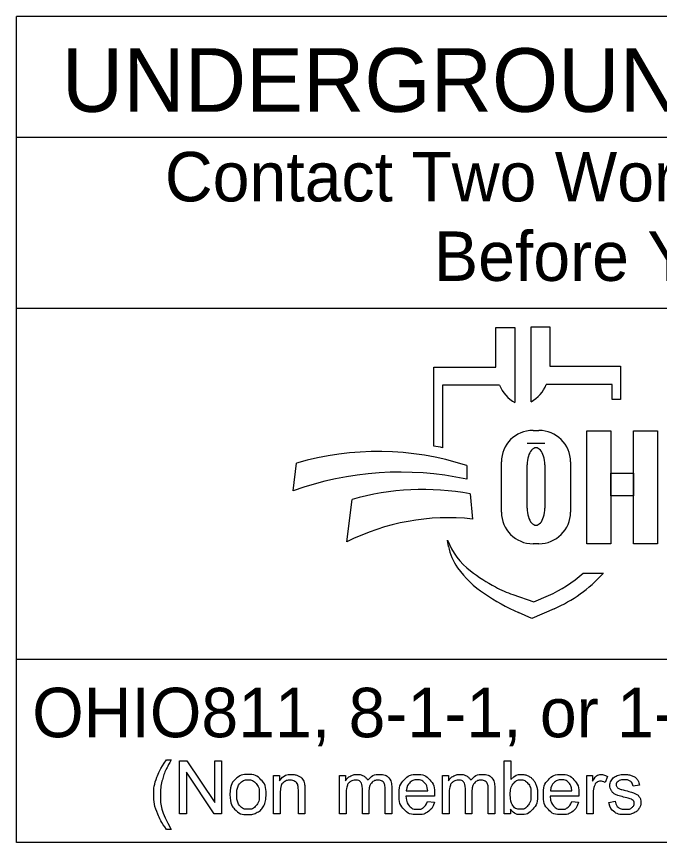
# Model space of a CAD drawing. Extents: x 0 to 34, y 0 to 22.
# Drawn here: x 14.755 to 16.574, y 1.201 to 3.539 of the extents above; entities that cross this region are included whole.
import ezdxf

# ---------------------------------------------------------------- set-up
doc = ezdxf.new("R2010")
doc.units = 0
doc.layers.add('SH_Data', color=7, linetype='Continuous')
doc.layers.add('SH_Text', color=7, linetype='Continuous')

msp = doc.modelspace()

# ---------------------------------------------------------------- linework, layer by layer
at = {"layer": 'SH_Data'}
for p, q in [((14.7549, 1.2013), (14.7549, 3.5388)), ((19.0049, 3.5388), (14.7549, 3.5388)), ((14.7549, 3.1972), (19.0049, 3.1972)), ((14.7549, 2.7138), (19.0049, 2.7138)), ((19.0049, 1.7191), (14.7549, 1.7191)), ((19.0049, 1.2013), (14.7549, 1.2013))]:
    msp.add_line(p, q, dxfattribs=at)
at = {"layer": 'SH_Text'}
for p, q in [((16.1109, 2.5468), (16.1109, 2.6583)), ((16.1109, 2.6583), (16.1645, 2.6583)), ((16.1645, 2.6583), (16.1645, 2.4462)), ((16.2102, 2.4485), (16.2102, 2.6606)), ((16.2102, 2.6606), (16.2638, 2.6606)), ((16.2638, 2.6606), (16.2638, 2.5491)), ((16.2638, 2.5491), (16.4631, 2.5491)), ((16.4631, 2.5491), (16.4631, 2.4553)), ((15.9349, 2.3229), (15.9349, 2.5468)), ((15.9349, 2.5468), (16.1109, 2.5468)), ((15.9602, 2.4953), (15.9602, 2.3185)), ((16.1213, 2.4953), (15.9602, 2.4953)), ((16.4398, 2.4977), (16.2534, 2.4977)), ((16.4398, 2.4553), (16.4398, 2.4977)), ((16.4631, 2.4553), (16.4398, 2.4553)), ((16.2159, 2.3676), (16.2324, 2.3676)), ((16.2492, 2.3306), (16.1994, 2.3306)), ((15.5376, 2.1966), (15.547, 2.2747)), ((16.0282, 2.2682), (16.0282, 2.2294)), ((16.1264, 2.1361), (16.1264, 2.2781)), ((16.1993, 2.1475), (16.1993, 2.2699)), ((16.2491, 2.2699), (16.2491, 2.1475)), ((16.3219, 2.2781), (16.3219, 2.1361)), ((16.0382, 2.1876), (16.0444, 2.1167)), ((15.6894, 2.0521), (15.7041, 2.1722)), ((15.9771, 2.0392), (15.974, 2.0571)), ((16.2324, 2.0467), (16.2159, 2.0467)), ((16.3574, 1.9633), (16.4148, 1.9633)), ((16.159, 1.9029), (16.2184, 1.8824)), ((16.2184, 1.8824), (16.2594, 1.9002)), ((16.2124, 1.8354), (16.175, 1.8519)), ((16.2756, 1.8629), (16.2124, 1.8354))]:
    msp.add_line(p, q, dxfattribs=at)
for points in [[(16.3683, 2.3666), (16.4363, 2.3666), (16.4363, 2.0466), (16.3683, 2.0466)], [(16.5005, 2.3666), (16.5684, 2.3666), (16.5684, 2.0466), (16.5005, 2.0466)], [(16.4363, 2.2467), (16.5005, 2.2467), (16.5005, 2.1827), (16.4363, 2.1827)]]:
    msp.add_lwpolyline(points, close=True, dxfattribs=at)
for points in [[(15.1795, 1.4351), (15.1927, 1.4351)], [(15.2162, 1.2824), (15.2162, 1.4326), (15.2366, 1.4326), (15.3156, 1.3146), (15.3156, 1.4326), (15.3346, 1.4326), (15.3346, 1.2824), (15.3142, 1.2824), (15.2352, 1.4003), (15.2352, 1.2824), (15.2162, 1.2824)], [(16.1517, 1.2824), (16.1346, 1.2824), (16.1346, 1.4326), (16.1531, 1.4326), (16.1531, 1.3791)], [(15.4822, 1.2824), (15.4822, 1.3913), (15.4988, 1.3913), (15.4988, 1.3758)], [(15.6686, 1.2824), (15.6686, 1.3913), (15.6851, 1.3913), (15.6851, 1.3759)], [(15.96, 1.2824), (15.96, 1.3913), (15.9765, 1.3913), (15.9765, 1.3759)], [(16.3678, 1.2824), (16.3678, 1.3913), (16.3844, 1.3913), (16.3844, 1.3748)], [(16.4268, 1.3878), (16.4204, 1.3707)], [(15.8161, 1.3571), (15.8161, 1.2824), (15.7977, 1.2824), (15.7977, 1.3509)], [(16.1075, 1.3571), (16.1075, 1.2824), (16.0891, 1.2824), (16.0891, 1.3509)], [(16.5168, 1.3631), (16.4987, 1.3607)], [(15.5006, 1.3418), (15.5006, 1.2824), (15.4822, 1.2824)], [(15.5705, 1.3493), (15.5705, 1.2824), (15.5521, 1.2824), (15.5521, 1.3486)], [(15.687, 1.3388), (15.687, 1.2824), (15.6686, 1.2824)], [(15.7517, 1.3456), (15.7517, 1.2824), (15.7333, 1.2824), (15.7333, 1.3531)], [(15.8572, 1.3472), (15.918, 1.3472)], [(15.9784, 1.3388), (15.9784, 1.2824), (15.96, 1.2824)], [(16.0431, 1.3456), (16.0431, 1.2824), (16.0246, 1.2824), (16.0246, 1.3531)], [(16.2652, 1.3472), (16.326, 1.3472)], [(16.3862, 1.3394), (16.3862, 1.2824), (16.3678, 1.2824)], [(15.9374, 1.3321), (15.8562, 1.3321)], [(15.9178, 1.3176), (15.9368, 1.3151)], [(16.3453, 1.3321), (16.2642, 1.3321)], [(16.3258, 1.3176), (16.3448, 1.3151)], [(16.4304, 1.3149), (16.4486, 1.3178)], [(16.1517, 1.296), (16.1517, 1.2824)], [(15.1927, 1.2382), (15.1795, 1.2382)]]:
    msp.add_lwpolyline(points, dxfattribs=at)
for centre, radius, start, end in [((16.2127, 2.5321), 0.0985, 201.9296, 240.7469), ((16.1621, 2.5344), 0.0985, 299.2531, 338.0704), ((16.2159, 2.2781), 0.0895, 90, 180), ((16.2324, 2.2781), 0.0895, 0, 90), ((15.8068, 1.5139), 0.8191, 79.2074, 81.0007), ((15.777, 1.4886), 0.8191, 72.1402, 106.3144), ((15.8401, 1.3575), 0.8919, 77.8238, 109.8274), ((15.904, 1.4679), 0.7322, 79.44, 105.8467), ((16.2159, 2.1361), 0.0895, 180, 270), ((16.2324, 2.1361), 0.0895, 270, 0), ((15.9761, 1.4847), 0.6357, 83.8248, 116.8021), ((16.1614, 2.1292), 0.2008, 201.0457, 232.5314), ((16.1184, 2.0633), 0.1433, 189.6817, 216.0884), ((16.2521, 2.1607), 0.3088, 216.0884, 235.7167), ((16.354, 2.3804), 0.5173, 232.5314, 241.794), ((16.116, 2.2307), 0.3602, 293.4582, 312.0712), ((16.116, 2.2307), 0.401, 293.4582, 317.8286), ((16.2688, 2.2216), 0.3371, 241.794, 250.9821), ((16.4186, 2.405), 0.6044, 235.7167, 246.2325)]:
    msp.add_arc(centre, radius, start, end, dxfattribs=at)
for centre, start_param, end_param in [((16.2242, 2.2699), 4.712389, 7.853982), ((16.2242, 2.1475), 1.570796, 4.712389)]:
    msp.add_ellipse(centre, major_axis=(0, 0.0484), ratio=0.514403, start_param=start_param, end_param=end_param, dxfattribs=at)
for points in [[(15.1795, 1.2382), (15.1642, 1.2575), (15.1537, 1.2833), (15.1431, 1.3091), (15.1431, 1.3368), (15.1431, 1.3611), (15.151, 1.3835), (15.1602, 1.4094), (15.1795, 1.4351)], [(15.1927, 1.4351), (15.1803, 1.4138), (15.1763, 1.4047), (15.1701, 1.3905), (15.1665, 1.3752), (15.1621, 1.356), (15.1621, 1.3367), (15.1621, 1.2874), (15.1927, 1.2382)], [(15.3587, 1.3368), (15.3587, 1.367), (15.3755, 1.3816), (15.3895, 1.3937), (15.4097, 1.3937), (15.4321, 1.3937), (15.4463, 1.379), (15.4606, 1.3643), (15.4606, 1.3384), (15.4606, 1.3174), (15.4543, 1.3054), (15.448, 1.2933), (15.4359, 1.2867), (15.4239, 1.28), (15.4097, 1.28), (15.3869, 1.28), (15.3728, 1.2947), (15.3587, 1.3093), (15.3587, 1.3368)], [(15.4988, 1.3758), (15.5108, 1.3937), (15.5334, 1.3937), (15.5432, 1.3937), (15.5515, 1.3901), (15.5597, 1.3866), (15.5638, 1.3809), (15.5679, 1.3751), (15.5695, 1.3672), (15.5705, 1.3621), (15.5705, 1.3493)], [(15.6851, 1.3759), (15.6902, 1.3839), (15.6987, 1.3888), (15.7072, 1.3937), (15.7181, 1.3937), (15.7302, 1.3937), (15.7379, 1.3886), (15.7456, 1.3836), (15.7488, 1.3746), (15.7618, 1.3937), (15.7825, 1.3937), (15.7987, 1.3937), (15.8074, 1.3847), (15.8161, 1.3757), (15.8161, 1.3571)], [(15.9368, 1.3151), (15.9323, 1.2985), (15.9201, 1.2892), (15.908, 1.28), (15.889, 1.28), (15.8652, 1.28), (15.8512, 1.2947), (15.8372, 1.3094), (15.8372, 1.3359), (15.8372, 1.3634), (15.8513, 1.3785), (15.8655, 1.3937), (15.888, 1.3937), (15.9098, 1.3937), (15.9236, 1.3788), (15.9375, 1.3639), (15.9375, 1.337), (15.9375, 1.3354), (15.9374, 1.3321)], [(15.9765, 1.3759), (15.9816, 1.3839), (15.9901, 1.3888), (15.9986, 1.3937), (16.0095, 1.3937), (16.0215, 1.3937), (16.0293, 1.3886), (16.037, 1.3836), (16.0402, 1.3746), (16.0531, 1.3937), (16.0738, 1.3937), (16.0901, 1.3937), (16.0988, 1.3847), (16.1075, 1.3757), (16.1075, 1.3571)], [(16.1531, 1.3791), (16.1647, 1.3937), (16.1829, 1.3937), (16.1929, 1.3937), (16.2019, 1.3896), (16.2108, 1.3856), (16.2166, 1.3782), (16.2224, 1.3709), (16.2257, 1.3606), (16.2289, 1.3502), (16.2289, 1.3385), (16.2289, 1.3105), (16.2151, 1.2953), (16.2013, 1.28), (16.1819, 1.28), (16.1627, 1.28), (16.1517, 1.296)], [(16.3448, 1.3151), (16.3403, 1.2985), (16.3281, 1.2892), (16.316, 1.28), (16.297, 1.28), (16.2731, 1.28), (16.2592, 1.2947), (16.2452, 1.3094), (16.2452, 1.3359), (16.2452, 1.3634), (16.2593, 1.3785), (16.2735, 1.3937), (16.296, 1.3937), (16.3178, 1.3937), (16.3316, 1.3788), (16.3454, 1.3639), (16.3454, 1.337), (16.3454, 1.3354), (16.3453, 1.3321)], [(16.3844, 1.3748), (16.3907, 1.3863), (16.3961, 1.39), (16.4014, 1.3937), (16.4079, 1.3937), (16.4172, 1.3937), (16.4268, 1.3878)], [(16.4486, 1.3178), (16.4501, 1.3068), (16.4571, 1.301), (16.4642, 1.2951), (16.4768, 1.2951), (16.4896, 1.2951), (16.4957, 1.3003), (16.5019, 1.3055), (16.5019, 1.3125), (16.5019, 1.3187), (16.4964, 1.3223), (16.4926, 1.3248), (16.4776, 1.3286), (16.4573, 1.3337), (16.4494, 1.3374), (16.4416, 1.3412), (16.4375, 1.3478), (16.4335, 1.3544), (16.4335, 1.3623), (16.4335, 1.3696), (16.4368, 1.3758), (16.4401, 1.382), (16.4459, 1.3861), (16.4502, 1.3893), (16.4576, 1.3915), (16.4651, 1.3937), (16.4736, 1.3937), (16.4864, 1.3937), (16.4961, 1.39), (16.5058, 1.3863), (16.5104, 1.38), (16.515, 1.3737), (16.5168, 1.3631)], [(15.3777, 1.3368), (15.3777, 1.3159), (15.3868, 1.3055), (15.3959, 1.2951), (15.4097, 1.2951), (15.4234, 1.2951), (15.4325, 1.3056), (15.4416, 1.316), (15.4416, 1.3374), (15.4416, 1.3576), (15.4324, 1.368), (15.4233, 1.3784), (15.4097, 1.3784), (15.3959, 1.3784), (15.3868, 1.3681), (15.3777, 1.3577), (15.3777, 1.3368)], [(15.5521, 1.3486), (15.5521, 1.3598), (15.55, 1.3654), (15.5478, 1.371), (15.5423, 1.3743), (15.5369, 1.3776), (15.5295, 1.3776), (15.5177, 1.3776), (15.5092, 1.3702), (15.5006, 1.3627), (15.5006, 1.3418)], [(15.7333, 1.3531), (15.7333, 1.3653), (15.7288, 1.3715), (15.7242, 1.3776), (15.714, 1.3776), (15.7062, 1.3776), (15.6996, 1.3735), (15.693, 1.3694), (15.69, 1.3616), (15.687, 1.3537), (15.687, 1.3388)], [(15.7977, 1.3509), (15.7977, 1.362), (15.7959, 1.3668), (15.7941, 1.3717), (15.7894, 1.3747), (15.7847, 1.3776), (15.7783, 1.3776), (15.7669, 1.3776), (15.7593, 1.37), (15.7517, 1.3624), (15.7517, 1.3456)], [(15.918, 1.3472), (15.9168, 1.361), (15.911, 1.3679), (15.9022, 1.3785), (15.8882, 1.3785), (15.8755, 1.3785), (15.8668, 1.37), (15.8581, 1.3615), (15.8572, 1.3472)], [(16.0246, 1.3531), (16.0246, 1.3653), (16.0201, 1.3715), (16.0156, 1.3776), (16.0054, 1.3776), (15.9976, 1.3776), (15.991, 1.3735), (15.9843, 1.3694), (15.9814, 1.3616), (15.9784, 1.3537), (15.9784, 1.3388)], [(16.0891, 1.3509), (16.0891, 1.362), (16.0873, 1.3668), (16.0855, 1.3717), (16.0808, 1.3747), (16.0761, 1.3776), (16.0697, 1.3776), (16.0582, 1.3776), (16.0506, 1.37), (16.0431, 1.3624), (16.0431, 1.3456)], [(16.1515, 1.3377), (16.1515, 1.3181), (16.1568, 1.3094), (16.1655, 1.2951), (16.1803, 1.2951), (16.1924, 1.2951), (16.2011, 1.3056), (16.2099, 1.3161), (16.2099, 1.3369), (16.2099, 1.3583), (16.2015, 1.3684), (16.1931, 1.3785), (16.1811, 1.3785), (16.169, 1.3785), (16.1603, 1.368), (16.1515, 1.3575), (16.1515, 1.3377)], [(16.326, 1.3472), (16.3248, 1.361), (16.319, 1.3679), (16.3102, 1.3785), (16.2962, 1.3785), (16.2835, 1.3785), (16.2748, 1.37), (16.2661, 1.3615), (16.2652, 1.3472)], [(16.4204, 1.3707), (16.4136, 1.3747), (16.4069, 1.3747), (16.4009, 1.3747), (16.3961, 1.371), (16.3913, 1.3674), (16.3893, 1.3609), (16.3862, 1.3511), (16.3862, 1.3394)], [(16.4987, 1.3607), (16.4975, 1.3691), (16.4916, 1.3738), (16.4857, 1.3785), (16.4749, 1.3785), (16.4622, 1.3785), (16.4567, 1.3743), (16.4513, 1.3701), (16.4513, 1.3645), (16.4513, 1.3609), (16.4536, 1.358), (16.4558, 1.3551), (16.4606, 1.3531), (16.4634, 1.3521), (16.4769, 1.3484), (16.4965, 1.3432), (16.5043, 1.3398), (16.512, 1.3365), (16.5165, 1.3302), (16.5209, 1.3238), (16.5209, 1.3144), (16.5209, 1.3052), (16.5155, 1.2971), (16.5101, 1.2889), (16.4999, 1.2845), (16.4898, 1.28), (16.477, 1.28), (16.4557, 1.28), (16.4446, 1.2888), (16.4334, 1.2976), (16.4304, 1.3149)], [(15.8562, 1.3321), (15.8572, 1.3142), (15.8663, 1.3046), (15.8755, 1.2951), (15.8891, 1.2951), (15.8992, 1.2951), (15.9064, 1.3005), (15.9136, 1.3058), (15.9178, 1.3176)], [(16.2642, 1.3321), (16.2652, 1.3142), (16.2743, 1.3046), (16.2835, 1.2951), (16.2971, 1.2951), (16.3072, 1.2951), (16.3144, 1.3005), (16.3216, 1.3058), (16.3258, 1.3176)]]:
    msp.add_open_spline(points, degree=3, dxfattribs=at)

# ---------------------------------------------------------------- texts
for s, height, p in [('UNDERGROUND UTILITIES', 0.18, (14.883, 3.2691)), ('Contact Two Working Days', 0.14, (15.1745, 3.0156)), ('Before You Dig', 0.14, (15.9357, 2.7906)), ('OHIO811, 8-1-1, or 1-800-362-2764', 0.14, (14.7993, 1.4991))]:
    msp.add_text(s, height=height, dxfattribs=at).set_placement(p)

doc.saveas('drawing.dxf')
